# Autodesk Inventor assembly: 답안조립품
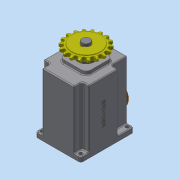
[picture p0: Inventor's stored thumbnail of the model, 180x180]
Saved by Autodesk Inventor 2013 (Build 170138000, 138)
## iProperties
Created: 2017-12
Part Number: 답안조립품
Document SubType Name: Assembly
Designer: dgall
Author: dgall
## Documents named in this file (17)
- C:\Users\dgall\Desktop\371207V1016\답안조립품.iam
- C:\Users\dgall\Desktop\371207V1016\본체.ipt
- C:\Users\dgall\Desktop\371207V1016\서브축.ipt
- C:\Users\dgall\Desktop\371207V1016\베어링 608.ipt
- C:\Users\dgall\Desktop\371207V1016\베어링 6003.ipt
- C:\Users\dgall\Desktop\371207V1016\키 5 x 5 x 18.ipt
- C:\Users\dgall\Desktop\371207V1016\커버.ipt
- C:\Users\dgall\Desktop\371207V1016\오일 실 17 32 8.ipt
- C:\Users\dgall\Desktop\371207V1016\메인축.ipt
- C:\Users\dgall\Desktop\371207V1016\스프로킷.ipt
- C:\Users\dgall\Desktop\371207V1016\멈춤나사 M3x8.ipt
- C:\Users\dgall\Desktop\371207V1016\가변스프링.ipt
- C:\Users\dgall\Desktop\371207V1016\부시.ipt
- C:\Users\dgall\Desktop\371207V1016\슬라이더.ipt
- C:\Users\dgall\Desktop\371207V1016\상부 캡.ipt
- C:\Users\dgall\Desktop\371207V1016\오일 실 8 22 7.ipt
- C:\Users\dgall\Desktop\371207V1016\볼트 M4 x 10.ipt
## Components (1 placed, 1 different names)
1. 가변스프링:1
